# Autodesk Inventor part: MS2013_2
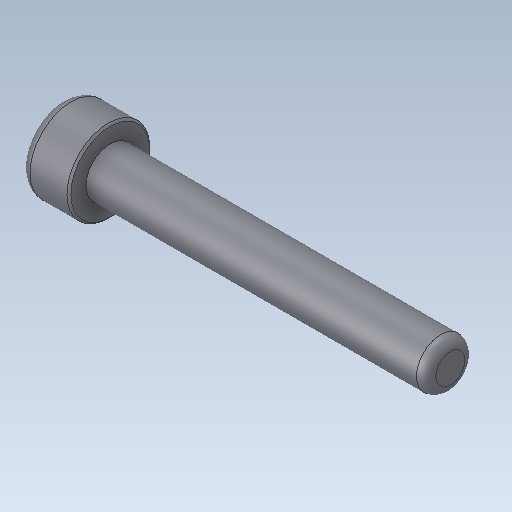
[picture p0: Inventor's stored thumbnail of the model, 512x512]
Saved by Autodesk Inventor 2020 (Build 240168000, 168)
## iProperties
Created: 2015-11
Part Number: MS2013_2
Material: Ogólny
Document SubType Name: Modeling
Designer: Tomasz
Density: 1 g/cm^3
Appearance: Domyślna
Sending System: SolidWorks 2017
Last Author: Tomasz
Last Saved: 2017-09-17
Author: Tomasz
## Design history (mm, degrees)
feature "Imported1"
node "Bryła1"
